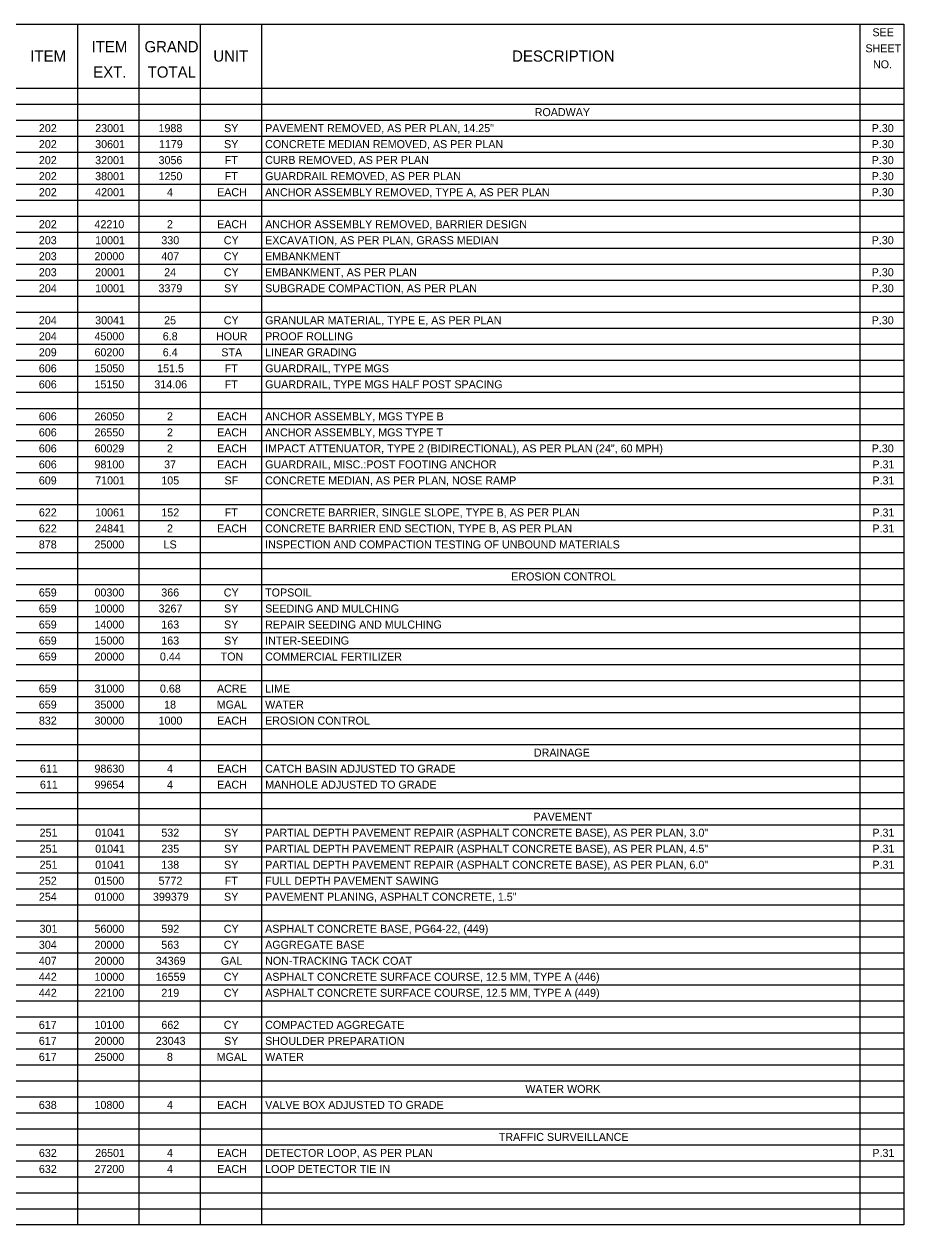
# Model space of a CAD drawing. Extents: x 12522 to 13018, y 1124 to 1902.
# Drawn here: x 12736.42 to 12751.8, y 1828.79 to 1849.79 of the extents above; entities that cross this region are included whole.
import ezdxf

# ---------------------------------------------------------------- set-up
doc = ezdxf.new("R2010")
doc.units = 0
for name, color, linetype in [('SC_Scratch1', 7, 'Continuous'), ('SH_Data', 7, 'Continuous'), ('SH_Text', 7, 'Continuous')]:
    doc.layers.add(name, color=color, linetype=linetype)

msp = doc.modelspace()

# ---------------------------------------------------------------- linework, layer by layer
at = {"layer": 'SC_Scratch1'}
msp.add_lwpolyline([(12721.301, 1849.791), (12751.801, 1849.791), (12751.801, 1828.791), (12721.301, 1828.791)], close=True, dxfattribs=at)
at = {"layer": 'SH_Data'}
for p, q in [((12737.359, 1849.791), (12737.359, 1828.791)), ((12738.43, 1849.791), (12738.43, 1828.791)), ((12739.501, 1849.791), (12739.501, 1828.791)), ((12740.571, 1849.791), (12740.571, 1828.791)), ((12751.03, 1849.791), (12751.03, 1828.791)), ((12721.301, 1848.671), (12751.804, 1848.671)), ((12721.301, 1848.391), (12751.804, 1848.391)), ((12721.301, 1848.111), (12751.804, 1848.111)), ((12721.301, 1847.831), (12751.804, 1847.831)), ((12721.301, 1847.551), (12751.804, 1847.551)), ((12721.301, 1847.271), (12751.804, 1847.271)), ((12721.301, 1846.991), (12751.804, 1846.991)), ((12721.301, 1846.711), (12751.804, 1846.711)), ((12721.301, 1846.431), (12751.804, 1846.431)), ((12721.301, 1846.151), (12751.804, 1846.151)), ((12721.301, 1845.871), (12751.804, 1845.871)), ((12721.301, 1845.591), (12751.804, 1845.591)), ((12721.301, 1845.311), (12751.804, 1845.311)), ((12721.301, 1845.031), (12751.804, 1845.031)), ((12721.301, 1844.751), (12751.804, 1844.751)), ((12721.301, 1844.471), (12751.804, 1844.471)), ((12721.301, 1844.191), (12751.804, 1844.191)), ((12721.301, 1843.911), (12751.804, 1843.911)), ((12721.301, 1843.631), (12751.804, 1843.631)), ((12721.301, 1843.351), (12751.804, 1843.351)), ((12721.301, 1843.071), (12751.804, 1843.071)), ((12721.301, 1842.791), (12751.804, 1842.791)), ((12721.301, 1842.511), (12751.804, 1842.511)), ((12721.301, 1842.231), (12751.804, 1842.231)), ((12721.301, 1841.951), (12751.804, 1841.951)), ((12721.301, 1841.671), (12751.804, 1841.671)), ((12721.301, 1841.391), (12751.804, 1841.391)), ((12721.301, 1841.111), (12751.804, 1841.111)), ((12721.301, 1840.831), (12751.804, 1840.831)), ((12721.301, 1840.551), (12751.804, 1840.551)), ((12721.301, 1840.271), (12751.804, 1840.271)), ((12721.301, 1839.991), (12751.804, 1839.991)), ((12721.301, 1839.711), (12751.804, 1839.711)), ((12721.301, 1839.431), (12751.804, 1839.431)), ((12721.301, 1839.151), (12751.804, 1839.151)), ((12721.301, 1838.871), (12751.804, 1838.871)), ((12721.301, 1838.591), (12751.804, 1838.591)), ((12721.301, 1838.311), (12751.804, 1838.311)), ((12721.301, 1838.031), (12751.804, 1838.031)), ((12721.301, 1837.751), (12751.804, 1837.751)), ((12721.301, 1837.471), (12751.804, 1837.471)), ((12721.301, 1837.191), (12751.804, 1837.191)), ((12721.301, 1836.911), (12751.804, 1836.911)), ((12721.301, 1836.631), (12751.804, 1836.631)), ((12721.301, 1836.351), (12751.804, 1836.351)), ((12721.301, 1836.071), (12751.804, 1836.071)), ((12721.301, 1835.791), (12751.804, 1835.791)), ((12721.301, 1835.511), (12751.804, 1835.511)), ((12721.301, 1835.231), (12751.804, 1835.231)), ((12721.301, 1834.951), (12751.804, 1834.951)), ((12721.301, 1834.671), (12751.804, 1834.671)), ((12721.301, 1834.391), (12751.804, 1834.391)), ((12721.301, 1834.111), (12751.804, 1834.111)), ((12721.301, 1833.831), (12751.804, 1833.831)), ((12721.301, 1833.551), (12751.804, 1833.551)), ((12721.301, 1833.271), (12751.804, 1833.271)), ((12721.301, 1832.991), (12751.804, 1832.991)), ((12721.301, 1832.711), (12751.804, 1832.711)), ((12721.301, 1832.431), (12751.804, 1832.431)), ((12721.301, 1832.151), (12751.804, 1832.151)), ((12721.301, 1831.871), (12751.804, 1831.871)), ((12721.301, 1831.591), (12751.804, 1831.591)), ((12721.301, 1831.311), (12751.804, 1831.311)), ((12721.301, 1831.031), (12751.804, 1831.031)), ((12721.301, 1830.751), (12751.804, 1830.751)), ((12721.301, 1830.471), (12751.804, 1830.471)), ((12721.301, 1830.191), (12751.804, 1830.191)), ((12721.301, 1829.911), (12751.804, 1829.911)), ((12721.301, 1829.631), (12751.804, 1829.631)), ((12721.301, 1829.351), (12751.804, 1829.351)), ((12721.301, 1829.071), (12751.804, 1829.071))]:
    msp.add_line(p, q, dxfattribs=at)

# ---------------------------------------------------------------- texts
at = {"layer": 'SH_Text'}
for s, height, p in [('SEE', 0.14, (12751.253, 1849.577)), ('ITEM', 0.196, (12737.602, 1849.297)), ('GRAND', 0.196, (12738.527, 1849.297)), ('ITEM', 0.196, (12736.531, 1849.133)), ('UNIT', 0.196, (12739.731, 1849.133)), ('DESCRIPTION', 0.196, (12744.954, 1849.133)), ('SHEET', 0.14, (12751.13, 1849.297)), ('TOTAL', 0.196, (12738.583, 1848.853)), ('NO.', 0.14, (12751.263, 1849.017)), ('EXT.', 0.196, (12737.631, 1848.853)), ('ROADWAY', 0.14, (12745.349, 1848.181)), ('202', 0.14, (12736.682, 1847.901)), ('23001', 0.14, (12737.666, 1847.901)), ('1988', 0.14, (12738.773, 1847.901)), ('SY', 0.14, (12739.919, 1847.901)), ('PAVEMENT REMOVED, AS PER PLAN, 14.25"', 0.14, (12740.637, 1847.901)), ('P.30', 0.14, (12751.24, 1847.901)), ('202', 0.14, (12736.682, 1847.621)), ('30601', 0.14, (12737.666, 1847.621)), ('1179', 0.14, (12738.78, 1847.621)), ('SY', 0.14, (12739.919, 1847.621)), ('CONCRETE MEDIAN REMOVED, AS PER PLAN', 0.14, (12740.637, 1847.621)), ('P.30', 0.14, (12751.24, 1847.621)), ('202', 0.14, (12736.682, 1847.341)), ('32001', 0.14, (12737.666, 1847.341)), ('3056', 0.14, (12738.774, 1847.341)), ('FT', 0.14, (12739.93, 1847.341)), ('CURB REMOVED, AS PER PLAN', 0.14, (12740.637, 1847.345)), ('P.30', 0.14, (12751.24, 1847.341)), ('202', 0.14, (12736.682, 1847.061)), ('38001', 0.14, (12737.666, 1847.061)), ('1250', 0.14, (12738.774, 1847.061)), ('FT', 0.14, (12739.93, 1847.061)), ('GUARDRAIL REMOVED, AS PER PLAN', 0.14, (12740.637, 1847.061)), ('P.30', 0.14, (12751.24, 1847.061)), ('202', 0.14, (12736.682, 1846.781)), ('42001', 0.14, (12737.666, 1846.781)), ('4', 0.14, (12738.921, 1846.781)), ('EACH', 0.14, (12739.798, 1846.781)), ('ANCHOR ASSEMBLY REMOVED, TYPE A, AS PER PLAN', 0.14, (12740.637, 1846.781)), ('P.30', 0.14, (12751.24, 1846.781)), ('202', 0.14, (12736.682, 1846.221)), ('42210', 0.14, (12737.654, 1846.221)), ('2', 0.14, (12738.921, 1846.221)), ('EACH', 0.14, (12739.798, 1846.221)), ('ANCHOR ASSEMBLY REMOVED, BARRIER DESIGN', 0.14, (12740.637, 1846.221)), ('203', 0.14, (12736.681, 1845.941)), ('10001', 0.14, (12737.666, 1845.941)), ('330', 0.14, (12738.823, 1845.941)), ('CY', 0.14, (12739.914, 1845.941)), ('EXCAVATION, AS PER PLAN, GRASS MEDIAN', 0.14, (12740.637, 1845.941)), ('P.30', 0.14, (12751.24, 1845.941)), ('203', 0.14, (12736.681, 1845.661)), ('20000', 0.14, (12737.654, 1845.661)), ('407', 0.14, (12738.822, 1845.661)), ('CY', 0.14, (12739.914, 1845.661)), ('EMBANKMENT', 0.14, (12740.637, 1845.661)), ('203', 0.14, (12736.681, 1845.381)), ('20001', 0.14, (12737.666, 1845.381)), ('24', 0.14, (12738.872, 1845.381)), ('CY', 0.14, (12739.914, 1845.381)), ('EMBANKMENT, AS PER PLAN', 0.14, (12740.637, 1845.381)), ('P.30', 0.14, (12751.24, 1845.381)), ('204', 0.14, (12736.682, 1845.101)), ('10001', 0.14, (12737.666, 1845.101)), ('3379', 0.14, (12738.773, 1845.101)), ('SY', 0.14, (12739.919, 1845.101)), ('SUBGRADE COMPACTION, AS PER PLAN', 0.14, (12740.637, 1845.101)), ('P.30', 0.14, (12751.24, 1845.101)), ('204', 0.14, (12736.682, 1844.541)), ('30041', 0.14, (12737.666, 1844.541)), ('25', 0.14, (12738.871, 1844.541)), ('CY', 0.14, (12739.914, 1844.541)), ('GRANULAR MATERIAL, TYPE E, AS PER PLAN', 0.14, (12740.637, 1844.541)), ('P.30', 0.14, (12751.24, 1844.541)), ('204', 0.14, (12736.682, 1844.261)), ('45000', 0.14, (12737.654, 1844.261)), ('6.8', 0.14, (12738.847, 1844.261)), ('HOUR', 0.14, (12739.778, 1844.261)), ('PROOF ROLLING', 0.14, (12740.637, 1844.261)), ('209', 0.14, (12736.681, 1843.981)), ('60200', 0.14, (12737.654, 1843.981)), ('6.4', 0.14, (12738.847, 1843.981)), ('STA', 0.14, (12739.871, 1843.981)), ('LINEAR GRADING', 0.14, (12740.637, 1843.981)), ('606', 0.14, (12736.681, 1843.701)), ('15050', 0.14, (12737.654, 1843.701)), ('151.5', 0.14, (12738.749, 1843.701)), ('FT', 0.14, (12739.93, 1843.701)), ('GUARDRAIL, TYPE MGS', 0.14, (12740.637, 1843.701)), ('606', 0.14, (12736.681, 1843.421)), ('15150', 0.14, (12737.654, 1843.421)), ('314.06', 0.14, (12738.7, 1843.421)), ('FT', 0.14, (12739.93, 1843.421)), ('GUARDRAIL, TYPE MGS HALF POST SPACING', 0.14, (12740.637, 1843.421)), ('606', 0.14, (12736.681, 1842.861)), ('26050', 0.14, (12737.654, 1842.861)), ('2', 0.14, (12738.921, 1842.861)), ('EACH', 0.14, (12739.798, 1842.861)), ('ANCHOR ASSEMBLY, MGS TYPE B', 0.14, (12740.637, 1842.861)), ('606', 0.14, (12736.681, 1842.581)), ('26550', 0.14, (12737.654, 1842.581)), ('2', 0.14, (12738.921, 1842.581)), ('EACH', 0.14, (12739.798, 1842.581)), ('ANCHOR ASSEMBLY, MGS TYPE T', 0.14, (12740.637, 1842.581)), ('606', 0.14, (12736.681, 1842.301)), ('60029', 0.14, (12737.654, 1842.301)), ('2', 0.14, (12738.921, 1842.301)), ('EACH', 0.14, (12739.798, 1842.301)), ('IMPACT ATTENUATOR, TYPE 2 (BIDIRECTIONAL), AS PER PLAN (24", 60 MPH)', 0.14, (12740.637, 1842.301)), ('P.30', 0.14, (12751.24, 1842.301)), ('606', 0.14, (12736.681, 1842.021)), ('98100', 0.14, (12737.654, 1842.021)), ('37', 0.14, (12738.871, 1842.021)), ('EACH', 0.14, (12739.798, 1842.021)), ('GUARDRAIL, MISC.:POST FOOTING ANCHOR', 0.14, (12740.637, 1842.021)), ('P.31', 0.14, (12751.252, 1842.021)), ('609', 0.14, (12736.681, 1841.741)), ('71001', 0.14, (12737.666, 1841.741)), ('105', 0.14, (12738.822, 1841.741)), ('SF', 0.14, (12739.927, 1841.741)), ('CONCRETE MEDIAN, AS PER PLAN, NOSE RAMP', 0.14, (12740.637, 1841.741)), ('P.31', 0.14, (12751.252, 1841.741)), ('622', 0.14, (12736.682, 1841.181)), ('10061', 0.14, (12737.666, 1841.181)), ('152', 0.14, (12738.823, 1841.181)), ('FT', 0.14, (12739.93, 1841.181)), ('CONCRETE BARRIER, SINGLE SLOPE, TYPE B, AS PER PLAN', 0.14, (12740.637, 1841.181)), ('P.31', 0.14, (12751.252, 1841.181)), ('622', 0.14, (12736.682, 1840.901)), ('24841', 0.14, (12737.666, 1840.901)), ('2', 0.14, (12738.921, 1840.901)), ('EACH', 0.14, (12739.798, 1840.901)), ('CONCRETE BARRIER END SECTION, TYPE B, AS PER PLAN', 0.14, (12740.637, 1840.901)), ('P.31', 0.14, (12751.252, 1840.901)), ('878', 0.14, (12736.681, 1840.621)), ('25000', 0.14, (12737.654, 1840.621)), ('LS', 0.14, (12738.862, 1840.621)), ('INSPECTION AND COMPACTION TESTING OF UNBOUND MATERIALS', 0.14, (12740.637, 1840.621)), ('EROSION CONTROL', 0.14, (12744.938, 1840.061)), ('659', 0.14, (12736.681, 1839.781)), ('00300', 0.14, (12737.654, 1839.781)), ('366', 0.14, (12738.822, 1839.781)), ('CY', 0.14, (12739.914, 1839.781)), ('TOPSOIL', 0.14, (12740.637, 1839.781)), ('659', 0.14, (12736.681, 1839.501)), ('10000', 0.14, (12737.654, 1839.501)), ('3267', 0.14, (12738.774, 1839.501)), ('SY', 0.14, (12739.919, 1839.501)), ('SEEDING AND MULCHING', 0.14, (12740.637, 1839.501)), ('659', 0.14, (12736.681, 1839.221)), ('14000', 0.14, (12737.654, 1839.221)), ('163', 0.14, (12738.822, 1839.221)), ('SY', 0.14, (12739.919, 1839.221)), ('REPAIR SEEDING AND MULCHING', 0.14, (12740.637, 1839.221)), ('659', 0.14, (12736.681, 1838.941)), ('15000', 0.14, (12737.654, 1838.941)), ('163', 0.14, (12738.822, 1838.941)), ('SY', 0.14, (12739.919, 1838.941)), ('INTER-SEEDING', 0.14, (12740.637, 1838.941)), ('659', 0.14, (12736.681, 1838.661)), ('20000', 0.14, (12737.654, 1838.661)), ('0.44', 0.14, (12738.798, 1838.661)), ('TON', 0.14, (12739.859, 1838.661)), ('COMMERCIAL FERTILIZER', 0.14, (12740.637, 1838.661)), ('659', 0.14, (12736.681, 1838.101)), ('31000', 0.14, (12737.654, 1838.101)), ('0.68', 0.14, (12738.798, 1838.101)), ('ACRE', 0.14, (12739.796, 1838.101)), ('LIME', 0.14, (12740.637, 1838.101)), ('659', 0.14, (12736.681, 1837.821)), ('35000', 0.14, (12737.654, 1837.821)), ('18', 0.14, (12738.871, 1837.821)), ('MGAL', 0.14, (12739.79, 1837.821)), ('WATER', 0.14, (12740.637, 1837.821)), ('832', 0.14, (12736.682, 1837.541)), ('30000', 0.14, (12737.654, 1837.541)), ('1000', 0.14, (12738.774, 1837.541)), ('EACH', 0.14, (12739.798, 1837.541)), ('EROSION CONTROL', 0.14, (12740.637, 1837.541)), ('DRAINAGE', 0.14, (12745.335, 1836.981)), ('611', 0.14, (12736.7, 1836.701)), ('98630', 0.14, (12737.654, 1836.701)), ('4', 0.14, (12738.921, 1836.701)), ('EACH', 0.14, (12739.798, 1836.701)), ('CATCH BASIN ADJUSTED TO GRADE', 0.14, (12740.637, 1836.701)), ('611', 0.14, (12736.7, 1836.421)), ('99654', 0.14, (12737.654, 1836.421)), ('4', 0.14, (12738.921, 1836.421)), ('EACH', 0.14, (12739.798, 1836.421)), ('MANHOLE ADJUSTED TO GRADE', 0.14, (12740.637, 1836.421)), ('PAVEMENT', 0.14, (12745.326, 1835.861)), ('251', 0.14, (12736.694, 1835.581)), ('01041', 0.14, (12737.666, 1835.581)), ('532', 0.14, (12738.823, 1835.581)), ('SY', 0.14, (12739.919, 1835.581)), ('PARTIAL DEPTH PAVEMENT REPAIR (ASPHALT CONCRETE BASE), AS PER PLAN, 3.0"', 0.14, (12740.637, 1835.581)), ('P.31', 0.14, (12751.252, 1835.581)), ('251', 0.14, (12736.694, 1835.301)), ('01041', 0.14, (12737.666, 1835.301)), ('235', 0.14, (12738.822, 1835.301)), ('SY', 0.14, (12739.919, 1835.301)), ('PARTIAL DEPTH PAVEMENT REPAIR (ASPHALT CONCRETE BASE), AS PER PLAN, 4.5"', 0.14, (12740.637, 1835.301)), ('P.31', 0.14, (12751.252, 1835.301)), ('251', 0.14, (12736.694, 1835.021)), ('01041', 0.14, (12737.666, 1835.021)), ('138', 0.14, (12738.822, 1835.021)), ('SY', 0.14, (12739.919, 1835.021)), ('PARTIAL DEPTH PAVEMENT REPAIR (ASPHALT CONCRETE BASE), AS PER PLAN, 6.0"', 0.14, (12740.637, 1835.021)), ('P.31', 0.14, (12751.252, 1835.021)), ('252', 0.14, (12736.682, 1834.741)), ('01500', 0.14, (12737.654, 1834.741)), ('5772', 0.14, (12738.774, 1834.741)), ('FT', 0.14, (12739.93, 1834.741)), ('FULL DEPTH PAVEMENT SAWING', 0.14, (12740.637, 1834.741)), ('254', 0.14, (12736.682, 1834.461)), ('01000', 0.14, (12737.654, 1834.461)), ('399379', 0.14, (12738.676, 1834.461)), ('SY', 0.14, (12739.919, 1834.461)), ('PAVEMENT PLANING, ASPHALT CONCRETE, 1.5"', 0.14, (12740.637, 1834.461)), ('301', 0.14, (12736.694, 1833.901)), ('56000', 0.14, (12737.654, 1833.901)), ('592', 0.14, (12738.823, 1833.901)), ('CY', 0.14, (12739.914, 1833.901)), ('ASPHALT CONCRETE BASE, PG64-22, (449)', 0.14, (12740.637, 1833.901)), ('304', 0.14, (12736.682, 1833.621)), ('20000', 0.14, (12737.654, 1833.621)), ('563', 0.14, (12738.822, 1833.621)), ('CY', 0.14, (12739.914, 1833.621)), ('AGGREGATE BASE', 0.14, (12740.637, 1833.621)), ('407', 0.14, (12736.681, 1833.341)), ('20000', 0.14, (12737.654, 1833.341)), ('34369', 0.14, (12738.725, 1833.341)), ('GAL', 0.14, (12739.863, 1833.341)), ('NON-TRACKING TACK COAT', 0.14, (12740.637, 1833.341)), ('442', 0.14, (12736.682, 1833.061)), ('10000', 0.14, (12737.654, 1833.061)), ('16559', 0.14, (12738.725, 1833.061)), ('CY', 0.14, (12739.914, 1833.061)), ('ASPHALT CONCRETE SURFACE COURSE, 12.5 MM, TYPE A (446)', 0.14, (12740.637, 1833.061)), ('442', 0.14, (12736.682, 1832.781)), ('22100', 0.14, (12737.654, 1832.781)), ('219', 0.14, (12738.822, 1832.781)), ('CY', 0.14, (12739.914, 1832.781)), ('ASPHALT CONCRETE SURFACE COURSE, 12.5 MM, TYPE A (449)', 0.14, (12740.637, 1832.781)), ('617', 0.14, (12736.681, 1832.221)), ('10100', 0.14, (12737.654, 1832.221)), ('662', 0.14, (12738.823, 1832.221)), ('CY', 0.14, (12739.914, 1832.221)), ('COMPACTED AGGREGATE', 0.14, (12740.637, 1832.221)), ('617', 0.14, (12736.681, 1831.941)), ('20000', 0.14, (12737.654, 1831.941)), ('23043', 0.14, (12738.725, 1831.941)), ('SY', 0.14, (12739.919, 1831.941)), ('SHOULDER PREPARATION', 0.14, (12740.637, 1831.941)), ('617', 0.14, (12736.681, 1831.661)), ('25000', 0.14, (12737.654, 1831.661)), ('8', 0.14, (12738.92, 1831.661)), ('MGAL', 0.14, (12739.79, 1831.661)), ('WATER', 0.14, (12740.637, 1831.661)), ('WATER WORK', 0.14, (12745.186, 1831.101)), ('638', 0.14, (12736.681, 1830.821)), ('10800', 0.14, (12737.654, 1830.821)), ('4', 0.14, (12738.921, 1830.821)), ('EACH', 0.14, (12739.798, 1830.821)), ('VALVE BOX ADJUSTED TO GRADE', 0.14, (12740.637, 1830.821)), ('TRAFFIC SURVEILLANCE', 0.14, (12744.721, 1830.261)), ('632', 0.14, (12736.682, 1829.981)), ('26501', 0.14, (12737.666, 1829.981)), ('4', 0.14, (12738.921, 1829.981)), ('EACH', 0.14, (12739.798, 1829.981)), ('DETECTOR LOOP, AS PER PLAN', 0.14, (12740.637, 1829.981)), ('P.31', 0.14, (12751.252, 1829.981)), ('632', 0.14, (12736.682, 1829.701)), ('27200', 0.14, (12737.654, 1829.701)), ('4', 0.14, (12738.921, 1829.701)), ('EACH', 0.14, (12739.798, 1829.701)), ('LOOP DETECTOR TIE IN', 0.14, (12740.637, 1829.701))]:
    msp.add_text(s, height=height, dxfattribs=at).set_placement(p)

doc.saveas('drawing.dxf')
